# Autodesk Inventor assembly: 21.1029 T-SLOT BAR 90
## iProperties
Created: 2006-12
Part Number: 21.1029 T-SLOT BAR 90
Document SubType Name: Assembly
Designer: Andy Moles
Mass: 62.769 g
Surface Area: 48.122 cm^2
Volume: 7.99469 cm^3
Density: 7.85134 g/cm^3
Author: Andy Moles
